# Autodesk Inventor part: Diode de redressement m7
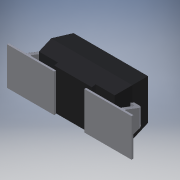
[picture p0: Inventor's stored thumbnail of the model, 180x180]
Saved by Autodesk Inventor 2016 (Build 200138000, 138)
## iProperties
Created: 2018-03
Part Number: Diode de redressement m7
Material: Générique
Document SubType Name: Modeling
Designer: Bruno
Density: 1 g/cm^3
Appearance: Par défaut
Author: Bruno
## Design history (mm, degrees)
feature "Composite1"
body "Srf1"
